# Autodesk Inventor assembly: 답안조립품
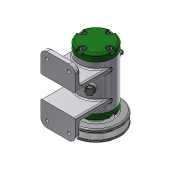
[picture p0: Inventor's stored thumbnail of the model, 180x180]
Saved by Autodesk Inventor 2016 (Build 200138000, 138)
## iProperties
Created: 2017-02
Part Number: 답안조립품
Material: 일반
Document SubType Name: Assembly
Designer: H
Author: H
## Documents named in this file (16)
- C:\Users\CAMTIC\Desktop\470207V1021\답안조립품.iam
- C:\Users\CAMTIC\Desktop\470207V1021\본체.ipt
- C:\Users\CAMTIC\Desktop\470207V1021\V벨트풀리.ipt
- C:\Users\CAMTIC\Desktop\470207V1021\너트 M 8.ipt
- C:\Users\CAMTIC\Desktop\470207V1021\니플 M 6 x 0.75.ipt
- C:\Users\CAMTIC\Desktop\470207V1021\뒤커버.ipt
- C:\Users\CAMTIC\Desktop\470207V1021\베어링 15 x 32 x 9.ipt
- C:\Users\CAMTIC\Desktop\470207V1021\볼트 M 6 x 8.ipt
- C:\Users\CAMTIC\Desktop\470207V1021\볼트 M4 x 12.ipt
- C:\Users\CAMTIC\Desktop\470207V1021\스프링와셔 8.ipt
- C:\Users\CAMTIC\Desktop\470207V1021\앞커버.ipt
- C:\Users\CAMTIC\Desktop\470207V1021\오일 실 15 25 7.ipt
- C:\Users\CAMTIC\Desktop\470207V1021\와셔 6x11.5.ipt
- C:\Users\CAMTIC\Desktop\470207V1021\와셔 8x17.ipt
- C:\Users\CAMTIC\Desktop\470207V1021\축.ipt
- C:\Users\CAMTIC\Desktop\470207V1021\키 3 x 3 x 12.ipt
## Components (11 placed, 3 different names)
1. V벨트풀리:1
2. KS B 2023 6002 - 15 x 32 x 9:1
3. KS B 2023 6002 - 15 x 32 x 9:2
4. ISO 4762 M4 x 12:2
5. ISO 4762 M4 x 12:3
6. ISO 4762 M4 x 12:4
7. ISO 4762 M4 x 12:5
8. ISO 4762 M4 x 12:1
9. ISO 4762 M4 x 12:6
10. ISO 4762 M4 x 12:7
11. ISO 4762 M4 x 12:8
